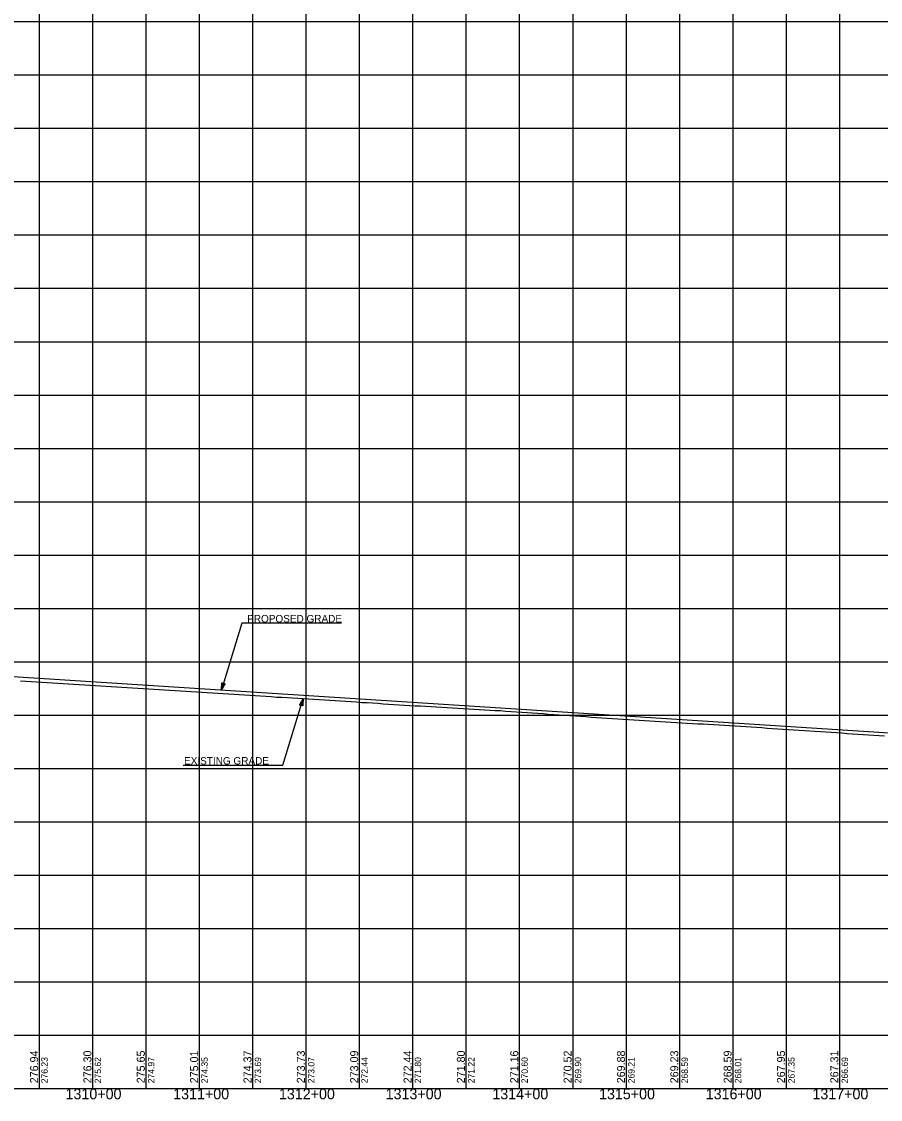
# Model space of a CAD drawing. Extents: x -90830 to 2015517, y -20856 to 836331.
# Drawn here: x 19857 to 20662, y -19397 to -18387 of the extents above; entities that cross this region are included whole.
import ezdxf

# ---------------------------------------------------------------- set-up
doc = ezdxf.new("R2010")
doc.units = 0
for name, color, linetype in [('Level 1', 7, 'Continuous'), ('RD_DDB_Profile_Elev', 7, 'Continuous'), ('RD_DDB_Profile_EX', 7, 'Continuous'), ('RD_DDB_Profile_PR', 7, 'Continuous'), ('RD_DDB_StaTX', 7, 'Continuous'), ('RD_DDB_StripGrade', 7, 'Continuous'), ('RD_GPK_Profile_Cell', 7, 'Continuous'), ('RD_PD_Final_TX', 7, 'Continuous')]:
    doc.layers.add(name, color=color, linetype=linetype)

msp = doc.modelspace()

# ---------------------------------------------------------------- linework, layer by layer
at = {"layer": 'Level 1'}
for p, q in [((19873.5, -17886.5), (19873.5, -18386.5)), ((19923.5, -17886.5), (19923.5, -18386.5)), ((19973.5, -17886.5), (19973.5, -18386.5)), ((20023.5, -17886.5), (20023.5, -18386.5)), ((20073.5, -17886.5), (20073.5, -18386.5)), ((20123.5, -17886.5), (20123.5, -18386.5)), ((20173.5, -17886.5), (20173.5, -18386.5)), ((20223.5, -17886.5), (20223.5, -18386.5)), ((20273.5, -17886.5), (20273.5, -18386.5)), ((20323.5, -17886.5), (20323.5, -18386.5)), ((20373.5, -17886.5), (20373.5, -18386.5)), ((20423.5, -17886.5), (20423.5, -18386.5)), ((20473.5, -17886.5), (20473.5, -18386.5)), ((20523.5, -17886.5), (20523.5, -18386.5)), ((20573.5, -17886.5), (20573.5, -18386.5)), ((20623.5, -17886.5), (20623.5, -18386.5)), ((19173.5, -18386.5), (20773.5, -18386.5)), ((19173.5, -18386.5), (20773.5, -18386.5)), ((19873.5, -18386.5), (19873.5, -18886.5)), ((19923.5, -18386.5), (19923.5, -18886.5)), ((19973.5, -18386.5), (19973.5, -18886.5)), ((20023.5, -18386.5), (20023.5, -18886.5)), ((20073.5, -18386.5), (20073.5, -18886.5)), ((20123.5, -18386.5), (20123.5, -18886.5)), ((20173.5, -18386.5), (20173.5, -18886.5)), ((20223.5, -18386.5), (20223.5, -18886.5)), ((20273.5, -18386.5), (20273.5, -18886.5)), ((20323.5, -18386.5), (20323.5, -18886.5)), ((20373.5, -18386.5), (20373.5, -18886.5)), ((20423.5, -18386.5), (20423.5, -18886.5)), ((20473.5, -18386.5), (20473.5, -18886.5)), ((20523.5, -18386.5), (20523.5, -18886.5)), ((20573.5, -18386.5), (20573.5, -18886.5)), ((20623.5, -18386.5), (20623.5, -18886.5)), ((19173.5, -18436.5), (20773.5, -18436.5)), ((19173.5, -18486.5), (20773.5, -18486.5)), ((19173.5, -18536.5), (20773.5, -18536.5)), ((19173.5, -18586.5), (20773.5, -18586.5)), ((19173.5, -18636.5), (20773.5, -18636.5)), ((19173.5, -18686.5), (20773.5, -18686.5)), ((19173.5, -18736.5), (20773.5, -18736.5)), ((19173.5, -18786.5), (20773.5, -18786.5)), ((19173.5, -18836.5), (20773.5, -18836.5)), ((19173.5, -18886.5), (20773.5, -18886.5)), ((19173.5, -18886.5), (20773.5, -18886.5)), ((19873.5, -18886.5), (19873.5, -19386.5)), ((19923.5, -18886.5), (19923.5, -19386.5)), ((19973.5, -18886.5), (19973.5, -19386.5)), ((20023.5, -18886.5), (20023.5, -19386.5)), ((20073.5, -18886.5), (20073.5, -19386.5)), ((20123.5, -18886.5), (20123.5, -19386.5)), ((20173.5, -18886.5), (20173.5, -19386.5)), ((20223.5, -18886.5), (20223.5, -19386.5)), ((20273.5, -18886.5), (20273.5, -19386.5)), ((20323.5, -18886.5), (20323.5, -19386.5)), ((20373.5, -18886.5), (20373.5, -19386.5)), ((20423.5, -18886.5), (20423.5, -19386.5)), ((20473.5, -18886.5), (20473.5, -19386.5)), ((20523.5, -18886.5), (20523.5, -19386.5)), ((20573.5, -18886.5), (20573.5, -19386.5)), ((20623.5, -18886.5), (20623.5, -19386.5)), ((19173.5, -18936.5), (20773.5, -18936.5)), ((19173.5, -18986.5), (20773.5, -18986.5)), ((19173.5, -19036.5), (20773.5, -19036.5)), ((19173.5, -19086.5), (20773.5, -19086.5)), ((19173.5, -19136.5), (20773.5, -19136.5)), ((19173.5, -19186.5), (20773.5, -19186.5)), ((19173.5, -19236.5), (20773.5, -19236.5)), ((19173.5, -19286.5), (20773.5, -19286.5)), ((19173.5, -19336.5), (20773.5, -19336.5)), ((19173.5, -19386.5), (20773.5, -19386.5))]:
    msp.add_line(p, q, dxfattribs=at)
at = {"layer": 'RD_DDB_Profile_EX'}
for points in [[(19855.9, -19004.2), (19860.9, -19004.6), (19865.9, -19004.9), (19870.9, -19005.2), (19875.9, -19005.5), (19880.9, -19005.8), (19885.9, -19006.2), (19890.9, -19006.5), (19895.9, -19006.8), (19900.9, -19007.1), (19905.9, -19007.4), (19910.9, -19007.7), (19915.9, -19008), (19920.9, -19008.3), (19925.9, -19008.6), (19930.9, -19008.9), (19935.9, -19009.3), (19940.9, -19009.6), (19945.9, -19010), (19950.9, -19010.3), (19955.9, -19010.6), (19960.9, -19010.9), (19965.9, -19011.2), (19970.9, -19011.5), (19975.9, -19011.8), (19980.9, -19012.1), (19985.9, -19012.4), (19990.9, -19012.7), (19995.9, -19013), (20000.9, -19013.3), (20005.9, -19013.6), (20010.9, -19013.9), (20015.9, -19014.2), (20020.9, -19014.6), (20025.9, -19014.9), (20030.9, -19015.2), (20035.9, -19015.6), (20040.9, -19015.9), (20045.9, -19016.3)], [(20045.9, -19016.3), (20050.9, -19016.6), (20055.9, -19016.9), (20060.9, -19017.3), (20065.9, -19017.6), (20070.9, -19017.9), (20075.9, -19018.2), (20080.9, -19018.5), (20085.9, -19018.8), (20090.9, -19019.1), (20095.9, -19019.5), (20100.9, -19019.8), (20105.9, -19020.1), (20110.9, -19020.4), (20115.9, -19020.7), (20120.9, -19021), (20125.9, -19021.3), (20130.9, -19021.6), (20135.9, -19021.9), (20140.9, -19022.2), (20145.9, -19022.5), (20150.9, -19022.9), (20155.9, -19023.2), (20160.9, -19023.5), (20165.9, -19023.8), (20170.9, -19024.1), (20175.9, -19024.5), (20180.9, -19024.8), (20185.9, -19025.1), (20190.9, -19025.4), (20195.9, -19025.8), (20200.9, -19026.1), (20205.9, -19026.5), (20210.9, -19026.8), (20215.9, -19027.1), (20220.9, -19027.4), (20225.9, -19027.7), (20230.9, -19027.9), (20235.9, -19028.2), (20240.9, -19028.5), (20245.9, -19028.8), (20250.9, -19029.1), (20255.9, -19029.4), (20260.9, -19029.7), (20265.9, -19030), (20270.9, -19030.3), (20275.9, -19030.6), (20280.9, -19030.9), (20285.9, -19031.2), (20290.9, -19031.5), (20295.9, -19031.7), (20300.9, -19032), (20305.9, -19032.3), (20310.9, -19032.7), (20315.9, -19033), (20320.9, -19033.3), (20325.9, -19033.7), (20330.9, -19034), (20335.9, -19034.4), (20340.9, -19034.8), (20345.9, -19035.1), (20350.9, -19035.5), (20355.9, -19035.8), (20360.9, -19036.1), (20365.9, -19036.5), (20370.9, -19036.8), (20375.9, -19037.2), (20380.9, -19037.6), (20385.9, -19037.9), (20390.9, -19038.3), (20395.9, -19038.6), (20400.9, -19038.9), (20405.9, -19039.3), (20410.9, -19039.6), (20415.9, -19040), (20420.9, -19040.3), (20425.9, -19040.6), (20430.9, -19040.9), (20435.9, -19041.3), (20440.9, -19041.6), (20445.9, -19041.9), (20450.9, -19042.2), (20455.9, -19042.5), (20460.9, -19042.8), (20465.9, -19043.1), (20470.9, -19043.4), (20475.9, -19043.7), (20480.9, -19043.9), (20485.9, -19044.2), (20490.9, -19044.5), (20495.9, -19044.8), (20500.9, -19045.1), (20505.9, -19045.4), (20510.9, -19045.7), (20515.9, -19046), (20520.9, -19046.3), (20525.9, -19046.6), (20530.9, -19046.9), (20535.9, -19047.2), (20540.9, -19047.6), (20545.9, -19047.9)], [(20545.9, -19047.9), (20550.9, -19048.2), (20555.9, -19048.6), (20560.9, -19048.9), (20565.9, -19049.2), (20570.9, -19049.6), (20575.9, -19049.9), (20580.9, -19050.3), (20585.9, -19050.6), (20590.9, -19050.9), (20595.9, -19051.3), (20600.9, -19051.6), (20605.9, -19051.9), (20610.9, -19052.2), (20615.9, -19052.6), (20620.9, -19052.9), (20625.9, -19053.2), (20630.9, -19053.6), (20635.9, -19053.9), (20640.9, -19054.2), (20645.9, -19054.6), (20650.9, -19054.9), (20655.9, -19055.2), (20660.9, -19055.5), (20665.9, -19055.8)]]:
    msp.add_lwpolyline(points, dxfattribs=at)
at = {"layer": 'RD_DDB_Profile_PR'}
msp.add_line((19803.5, -18997.3), (21178.5, -19085.6), dxfattribs=at)
at = {"layer": 'RD_GPK_Profile_Cell'}
msp.add_line((4823.5, -19386.5), (75223.5, -19386.5), dxfattribs=at)
at = {"layer": 'RD_PD_Final_TX'}
for p, q in [((20044.4, -19012.8), (20044.8, -19006.1)), ((20046.3, -19006.6), (20044.4, -19012.8)), ((20044.4, -19012.8), (20047.9, -19007.1)), ((20044.8, -19006.1), (20047.9, -19007.1)), ((20120.9, -19021), (20117.5, -19026.7)), ((20120.6, -19027.7), (20117.5, -19026.7)), ((20119.1, -19027.2), (20120.9, -19021)), ((20120.9, -19021), (20120.6, -19027.7))]:
    msp.add_line(p, q, dxfattribs=at)
for points in [[(20156.9, -18950.4), (20063.5, -18950.4), (20044.4, -19012.8)], [(20046.3, -19006.7), (20044.5, -19012.4), (20046.2, -19006.6), (20044.5, -19012.1), (20046.2, -19006.6), (20044.5, -19011.9), (20046.1, -19006.6), (20044.5, -19011.7), (20046, -19006.6), (20044.6, -19011.4), (20045.9, -19006.5), (20044.6, -19011), (20045.8, -19006.5), (20044.6, -19010.7), (20045.8, -19006.5), (20044.6, -19010.3), (20045.7, -19006.5), (20044.6, -19010.1), (20045.7, -19006.4), (20044.6, -19009.8), (20045.6, -19006.4), (20044.7, -19009.4), (20045.5, -19006.4), (20044.7, -19009), (20045.4, -19006.4), (20044.7, -19008.7), (20045.3, -19006.3), (20044.7, -19008.3), (20045.3, -19006.4), (20044.8, -19007.9), (20045.2, -19006.3), (20044.8, -19007.6), (20045.1, -19006.3), (20044.8, -19007.3), (20045, -19006.2), (20044.8, -19006.9), (20045, -19006.3), (20044.8, -19006.5), (20044.9, -19006.3)], [(20044.6, -19012.4), (20046.3, -19006.7), (20044.7, -19012.2), (20046.4, -19006.7), (20044.8, -19012), (20046.5, -19006.7), (20044.9, -19011.9), (20046.5, -19006.7), (20045, -19011.7), (20046.6, -19006.7), (20045.2, -19011.5), (20046.6, -19006.7), (20045.3, -19011.3), (20046.7, -19006.8), (20045.5, -19011), (20046.8, -19006.8), (20045.6, -19010.7), (20046.9, -19006.8), (20045.7, -19010.5), (20046.9, -19006.8), (20045.9, -19010.3), (20047, -19006.8), (20046, -19010), (20047, -19006.9), (20046.2, -19009.7), (20047.1, -19006.9), (20046.4, -19009.4), (20047.2, -19006.9), (20046.6, -19009.1), (20047.2, -19006.9), (20046.7, -19008.8), (20047.3, -19007), (20046.9, -19008.6), (20047.4, -19007), (20047, -19008.4), (20047.4, -19007), (20047.2, -19008), (20047.5, -19007), (20047.3, -19007.8), (20047.6, -19007), (20047.5, -19007.7), (20047.7, -19007.1), (20047.8, -19007.1), (20047.7, -19007.1)], [(20008.5, -19083.4), (20101.9, -19083.4), (20120.9, -19021)], [(20120.8, -19021.4), (20119, -19027.1), (20120.7, -19021.6), (20119, -19027.1), (20120.6, -19021.8), (20118.9, -19027.1), (20120.5, -19021.9), (20118.9, -19027.1), (20120.3, -19022.1), (20118.8, -19027.1), (20120.2, -19022.3), (20118.7, -19027.1), (20120.1, -19022.6), (20118.7, -19027.1), (20119.9, -19022.8), (20118.6, -19027), (20119.8, -19023.1), (20118.5, -19027), (20119.7, -19023.3), (20118.5, -19027), (20119.5, -19023.5), (20118.4, -19027), (20119.3, -19023.8), (20118.4, -19026.9), (20119.1, -19024.2), (20118.3, -19026.9), (20119, -19024.4), (20118.2, -19026.9), (20118.8, -19024.7), (20118.2, -19026.9), (20118.7, -19025), (20118.1, -19026.9), (20118.5, -19025.2), (20118, -19026.8), (20118.3, -19025.4), (20118, -19026.8), (20118.2, -19025.8), (20117.9, -19026.8), (20118.1, -19026), (20117.8, -19026.8), (20117.9, -19026.1), (20117.7, -19026.7), (20117.6, -19026.7), (20117.7, -19026.7)], [(20119.1, -19027.2), (20120.9, -19021.4), (20119.2, -19027.2), (20120.9, -19021.7), (20119.2, -19027.2), (20120.9, -19021.9), (20119.3, -19027.2), (20120.9, -19022.1), (20119.4, -19027.2), (20120.8, -19022.5), (20119.5, -19027.3), (20120.8, -19022.8), (20119.5, -19027.3), (20120.8, -19023.1), (20119.6, -19027.3), (20120.8, -19023.5), (20119.7, -19027.3), (20120.7, -19023.7), (20119.7, -19027.4), (20120.7, -19024), (20119.8, -19027.4), (20120.7, -19024.4), (20119.9, -19027.4), (20120.7, -19024.8), (20120, -19027.4), (20120.7, -19025.1), (20120, -19027.5), (20120.7, -19025.5), (20120.1, -19027.5), (20120.6, -19025.9), (20120.2, -19027.5), (20120.6, -19026.2), (20120.3, -19027.5), (20120.6, -19026.5), (20120.3, -19027.6), (20120.6, -19026.9), (20120.4, -19027.5), (20120.6, -19027.3), (20120.5, -19027.5)]]:
    msp.add_lwpolyline(points, dxfattribs=at)

# ---------------------------------------------------------------- texts
at = {"layer": 'RD_DDB_Profile_Elev'}
for s, p in [('276.94', (19872.5, -19381.5)), ('276.30', (19922.5, -19381.5)), ('275.65', (19972.5, -19381.5)), ('275.01', (20022.5, -19381.5)), ('274.37', (20072.5, -19381.5)), ('273.73', (20122.5, -19381.5)), ('273.09', (20172.5, -19381.5)), ('272.44', (20222.5, -19381.5)), ('271.80', (20272.5, -19381.5)), ('271.16', (20322.5, -19381.5)), ('270.52', (20372.5, -19381.5)), ('269.88', (20422.5, -19381.5)), ('269.23', (20472.5, -19381.5)), ('268.59', (20522.5, -19381.5)), ('267.95', (20572.5, -19381.5)), ('267.31', (20622.5, -19381.5))]:
    msp.add_text(s, height=7.5, rotation=90, dxfattribs=at).set_placement(p)
at = {"layer": 'RD_DDB_StaTX'}
for s, p in [('1310+00', (19898.2, -19396.5)), ('1311+00', (19999.1, -19396.5)), ('1312+00', (20098.2, -19396.5)), ('1313+00', (20198.2, -19396.5)), ('1314+00', (20298.2, -19396.5)), ('1315+00', (20398.2, -19396.5)), ('1316+00', (20498.2, -19396.5)), ('1317+00', (20598.2, -19396.5))]:
    msp.add_text(s, height=10, dxfattribs=at).set_placement(p)
at = {"layer": 'RD_DDB_StripGrade'}
for s, p in [('276.23', (19881.5, -19381.5)), ('275.62', (19931.5, -19381.5)), ('274.97', (19981.5, -19381.5)), ('274.35', (20031.5, -19381.5)), ('273.69', (20081.5, -19381.5)), ('273.07', (20131.5, -19381.5)), ('272.44', (20181.5, -19381.5)), ('271.80', (20231.5, -19381.5)), ('271.22', (20281.5, -19381.5)), ('270.60', (20331.5, -19381.5)), ('269.90', (20381.5, -19381.5)), ('269.21', (20431.5, -19381.5)), ('268.59', (20481.5, -19381.5)), ('268.01', (20531.5, -19381.5)), ('267.35', (20581.5, -19381.5)), ('266.69', (20631.5, -19381.5))]:
    msp.add_text(s, height=6, rotation=90, dxfattribs=at).set_placement(p)
at = {"layer": 'RD_PD_Final_TX'}
for s, p in [('PROPOSED GRADE', (20068.4, -18949.6)), ('EXISTING GRADE', (20009.3, -19082.8))]:
    msp.add_text(s, height=7, dxfattribs=at).set_placement(p)

doc.saveas('drawing.dxf')
